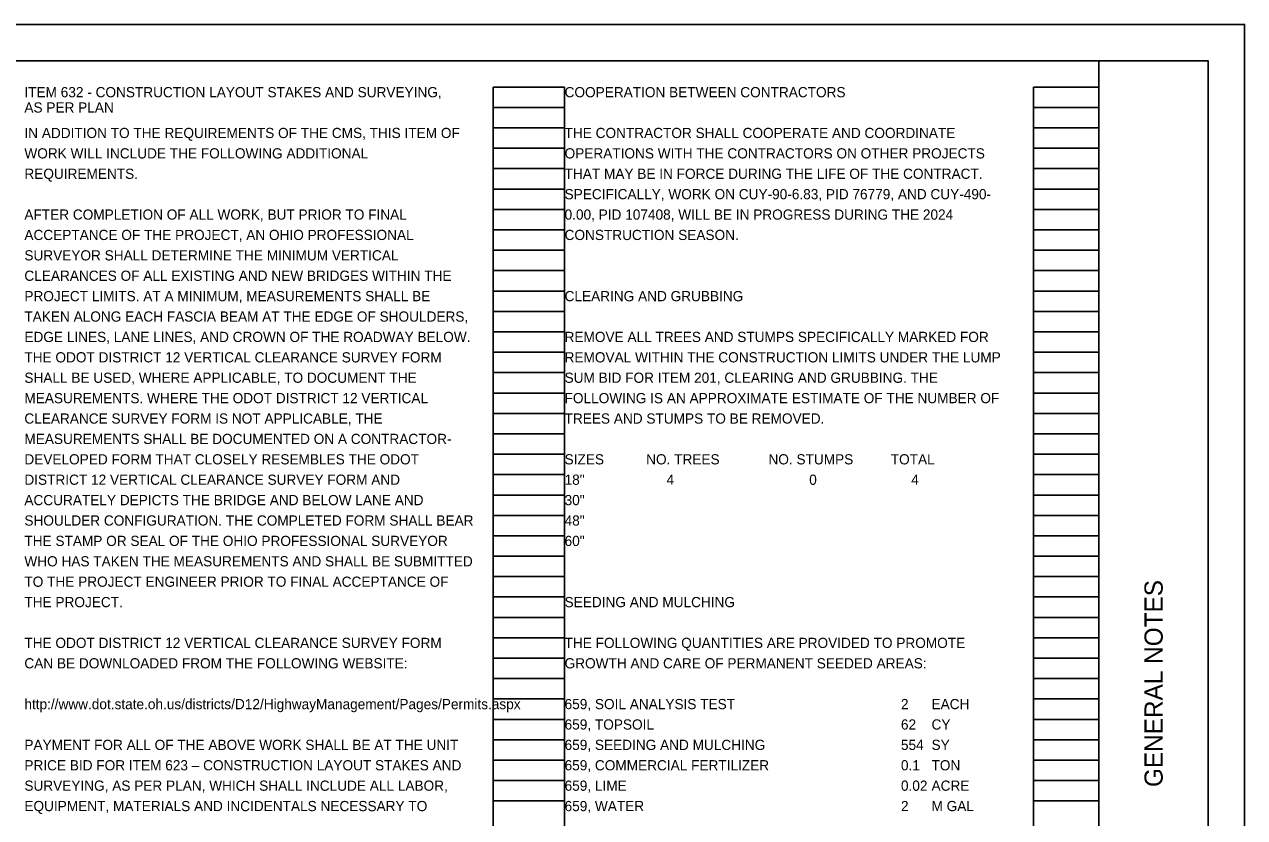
# Model space of a CAD drawing. Extents: x 0 to 34, y 0 to 22.
# Drawn here: x 17.24 to 34, y 11.11 to 22 of the extents above; entities that cross this region are included whole.
import ezdxf

# ---------------------------------------------------------------- set-up
doc = ezdxf.new("R2010")
doc.units = 0
for name, color, linetype in [('SH_Border', 7, 'Continuous'), ('SH_Cut_Line', 7, 'Continuous'), ('SH_Data', 7, 'Continuous'), ('SH_Text', 7, 'Continuous')]:
    doc.layers.add(name, color=color, linetype=linetype)

msp = doc.modelspace()

# ---------------------------------------------------------------- linework, layer by layer
at = {"layer": 'SH_Border'}
msp.add_line((32, 0.5), (32, 21.5), dxfattribs=at)
msp.add_lwpolyline([(1.5, 21.5), (33.5, 21.5), (33.5, 0.5), (1.5, 0.5)], close=True, dxfattribs=at)
at = {"layer": 'SH_Cut_Line'}
msp.add_lwpolyline([(0, 0), (34, 0), (34, 22), (0, 22)], close=True, dxfattribs=at)
at = {"layer": 'SH_Data'}
for p, q in [((23.68, 0.98), (23.68, 21.14)), ((23.68, 21.14), (24.66, 21.14)), ((24.66, 0.98), (24.66, 21.14)), ((31.1, 0.98), (31.1, 21.14)), ((31.1, 21.14), (32, 21.14)), ((32, 0.98), (32, 21.14)), ((23.68, 20.86), (24.66, 20.86)), ((31.1, 20.86), (32, 20.86)), ((23.68, 20.58), (24.66, 20.58)), ((31.1, 20.58), (32, 20.58)), ((23.68, 20.3), (24.66, 20.3)), ((31.1, 20.3), (32, 20.3)), ((23.68, 20.02), (24.66, 20.02)), ((31.1, 20.02), (32, 20.02)), ((23.68, 19.74), (24.66, 19.74)), ((31.1, 19.74), (32, 19.74)), ((23.68, 19.46), (24.66, 19.46)), ((31.1, 19.46), (32, 19.46)), ((23.68, 19.18), (24.66, 19.18)), ((31.1, 19.18), (32, 19.18)), ((23.68, 18.9), (24.66, 18.9)), ((31.1, 18.9), (32, 18.9)), ((23.68, 18.62), (24.66, 18.62)), ((31.1, 18.62), (32, 18.62)), ((23.68, 18.34), (24.66, 18.34)), ((31.1, 18.34), (32, 18.34)), ((23.68, 18.06), (24.66, 18.06)), ((31.1, 18.06), (32, 18.06)), ((23.68, 17.78), (24.66, 17.78)), ((31.1, 17.78), (32, 17.78)), ((23.68, 17.5), (24.66, 17.5)), ((31.1, 17.5), (32, 17.5)), ((23.68, 17.22), (24.66, 17.22)), ((31.1, 17.22), (32, 17.22)), ((23.68, 16.94), (24.66, 16.94)), ((31.1, 16.94), (32, 16.94)), ((23.68, 16.66), (24.66, 16.66)), ((31.1, 16.66), (32, 16.66)), ((23.68, 16.38), (24.66, 16.38)), ((31.1, 16.38), (32, 16.38)), ((23.68, 16.1), (24.66, 16.1)), ((31.1, 16.1), (32, 16.1)), ((23.68, 15.82), (24.66, 15.82)), ((31.1, 15.82), (32, 15.82)), ((23.68, 15.54), (24.66, 15.54)), ((31.1, 15.54), (32, 15.54)), ((23.68, 15.26), (24.66, 15.26)), ((31.1, 15.26), (32, 15.26)), ((23.68, 14.98), (24.66, 14.98)), ((31.1, 14.98), (32, 14.98)), ((23.68, 14.7), (24.66, 14.7)), ((31.1, 14.7), (32, 14.7)), ((23.68, 14.42), (24.66, 14.42)), ((31.1, 14.42), (32, 14.42)), ((23.68, 14.14), (24.66, 14.14)), ((31.1, 14.14), (32, 14.14)), ((23.68, 13.86), (24.66, 13.86)), ((31.1, 13.86), (32, 13.86)), ((23.68, 13.58), (24.66, 13.58)), ((31.1, 13.58), (32, 13.58)), ((23.68, 13.3), (24.66, 13.3)), ((31.1, 13.3), (32, 13.3)), ((23.68, 13.02), (24.66, 13.02)), ((31.1, 13.02), (32, 13.02)), ((23.68, 12.74), (24.66, 12.74)), ((31.1, 12.74), (32, 12.74)), ((23.68, 12.46), (24.66, 12.46)), ((31.1, 12.46), (32, 12.46)), ((23.68, 12.18), (24.66, 12.18)), ((31.1, 12.18), (32, 12.18)), ((23.68, 11.9), (24.66, 11.9)), ((31.1, 11.9), (32, 11.9)), ((23.68, 11.62), (24.66, 11.62)), ((31.1, 11.62), (32, 11.62)), ((23.68, 11.34), (24.66, 11.34)), ((31.1, 11.34), (32, 11.34))]:
    msp.add_line(p, q, dxfattribs=at)

# ---------------------------------------------------------------- texts
msp.add_text('GENERAL NOTES', height=0.25, rotation=90, dxfattribs=at).set_placement((32.875, 11.531))
at = {"layer": 'SH_Text'}
for s, p in [('ITEM 632 - CONSTRUCTION LAYOUT STAKES AND SURVEYING, ', (17.24, 21)), ('COOPERATION BETWEEN CONTRACTORS', (24.66, 21)), ('AS PER PLAN', (17.24, 20.79)), ('IN ADDITION TO THE REQUIREMENTS OF THE CMS, THIS ITEM OF ', (17.24, 20.44)), ('THE CONTRACTOR SHALL COOPERATE AND COORDINATE ', (24.66, 20.44)), ('WORK WILL INCLUDE THE FOLLOWING ADDITIONAL ', (17.24, 20.16)), ('OPERATIONS WITH THE CONTRACTORS ON OTHER PROJECTS ', (24.66, 20.16)), ('REQUIREMENTS.', (17.24, 19.88)), ('THAT MAY BE IN FORCE DURING THE LIFE OF THE CONTRACT. ', (24.66, 19.88)), ('SPECIFICALLY, WORK ON CUY-90-6.83, PID 76779, AND CUY-490-', (24.66, 19.6)), ('AFTER COMPLETION OF ALL WORK, BUT PRIOR TO FINAL ', (17.24, 19.32)), ('0.00, PID 107408, WILL BE IN PROGRESS DURING THE 2024 ', (24.66, 19.32)), ('ACCEPTANCE OF THE PROJECT, AN OHIO PROFESSIONAL ', (17.24, 19.04)), ('CONSTRUCTION SEASON.', (24.66, 19.04)), ('SURVEYOR SHALL DETERMINE THE MINIMUM VERTICAL ', (17.24, 18.76)), ('CLEARANCES OF ALL EXISTING AND NEW BRIDGES WITHIN THE ', (17.24, 18.48)), ('PROJECT LIMITS. AT A MINIMUM, MEASUREMENTS SHALL BE ', (17.24, 18.2)), ('CLEARING AND GRUBBING', (24.66, 18.2)), ('TAKEN ALONG EACH FASCIA BEAM AT THE EDGE OF SHOULDERS, ', (17.24, 17.92)), ('EDGE LINES, LANE LINES, AND CROWN OF THE ROADWAY BELOW. ', (17.24, 17.64)), ('REMOVE ALL TREES AND STUMPS SPECIFICALLY MARKED FOR ', (24.66, 17.64)), ('THE ODOT DISTRICT 12 VERTICAL CLEARANCE SURVEY FORM ', (17.24, 17.36)), ('REMOVAL WITHIN THE CONSTRUCTION LIMITS UNDER THE LUMP ', (24.66, 17.36)), ('SHALL BE USED, WHERE APPLICABLE, TO DOCUMENT THE ', (17.24, 17.08)), ('SUM BID FOR ITEM 201, CLEARING AND GRUBBING. THE ', (24.66, 17.08)), ('MEASUREMENTS. WHERE THE ODOT DISTRICT 12 VERTICAL ', (17.24, 16.8)), ('FOLLOWING IS AN APPROXIMATE ESTIMATE OF THE NUMBER OF ', (24.66, 16.8)), ('CLEARANCE SURVEY FORM IS NOT APPLICABLE, THE ', (17.24, 16.52)), ('TREES AND STUMPS TO BE REMOVED.', (24.66, 16.52)), ('MEASUREMENTS SHALL BE DOCUMENTED ON A CONTRACTOR-', (17.24, 16.24)), ('DEVELOPED FORM THAT CLOSELY RESEMBLES THE ODOT ', (17.24, 15.96)), ('SIZES ', (24.66, 15.96)), ('NO. TREES ', (25.78, 15.96)), ('NO. STUMPS ', (27.46, 15.96)), ('TOTAL', (29.14, 15.96)), ('DISTRICT 12 VERTICAL CLEARANCE SURVEY FORM AND ', (17.24, 15.68)), ('18"', (24.66, 15.68)), ('4', (26.06, 15.68)), ('0', (28.02, 15.68)), ('4', (29.42, 15.68)), ('ACCURATELY DEPICTS THE BRIDGE AND BELOW LANE AND ', (17.24, 15.4)), ('30"', (24.66, 15.4)), ('SHOULDER CONFIGURATION. THE COMPLETED FORM SHALL BEAR ', (17.24, 15.12)), ('48"', (24.66, 15.12)), ('THE STAMP OR SEAL OF THE OHIO PROFESSIONAL SURVEYOR ', (17.24, 14.84)), ('60" ', (24.66, 14.84)), ('WHO HAS TAKEN THE MEASUREMENTS AND SHALL BE SUBMITTED ', (17.24, 14.56)), ('TO THE PROJECT ENGINEER PRIOR TO FINAL ACCEPTANCE OF ', (17.24, 14.28)), ('THE PROJECT.', (17.24, 14)), ('SEEDING AND MULCHING', (24.66, 14)), ('THE ODOT DISTRICT 12 VERTICAL CLEARANCE SURVEY FORM ', (17.24, 13.44)), ('THE FOLLOWING QUANTITIES ARE PROVIDED TO PROMOTE ', (24.66, 13.44)), ('CAN BE DOWNLOADED FROM THE FOLLOWING WEBSITE:', (17.24, 13.16)), ('GROWTH AND CARE OF PERMANENT SEEDED AREAS:', (24.66, 13.16)), ('http://www.dot.state.oh.us/districts/D12/HighwayManagement/Pages/Permits.aspx', (17.24, 12.6)), ('659, SOIL ANALYSIS TEST', (24.66, 12.6)), ('2', (29.28, 12.6)), ('EACH', (29.7, 12.6)), ('659, TOPSOIL', (24.66, 12.32)), ('62', (29.28, 12.32)), ('CY', (29.7, 12.32)), ('PAYMENT FOR ALL OF THE ABOVE WORK SHALL BE AT THE UNIT ', (17.24, 12.04)), ('659, SEEDING AND MULCHING', (24.66, 12.04)), ('554', (29.28, 12.04)), ('SY', (29.7, 12.04)), ('PRICE BID FOR ITEM 623 – CONSTRUCTION LAYOUT STAKES AND ', (17.24, 11.76)), ('659, COMMERCIAL FERTILIZER', (24.66, 11.76)), ('0.1', (29.28, 11.76)), ('TON', (29.7, 11.76)), ('SURVEYING, AS PER PLAN, WHICH SHALL INCLUDE ALL LABOR, ', (17.24, 11.48)), ('659, LIME', (24.66, 11.48)), ('0.02', (29.28, 11.48)), ('ACRE', (29.7, 11.48)), ('EQUIPMENT, MATERIALS AND INCIDENTALS NECESSARY TO ', (17.24, 11.2)), ('659, WATER', (24.66, 11.2)), ('2', (29.28, 11.2)), ('M GAL', (29.7, 11.2))]:
    msp.add_text(s, height=0.14, dxfattribs=at).set_placement(p)

doc.saveas('drawing.dxf')
